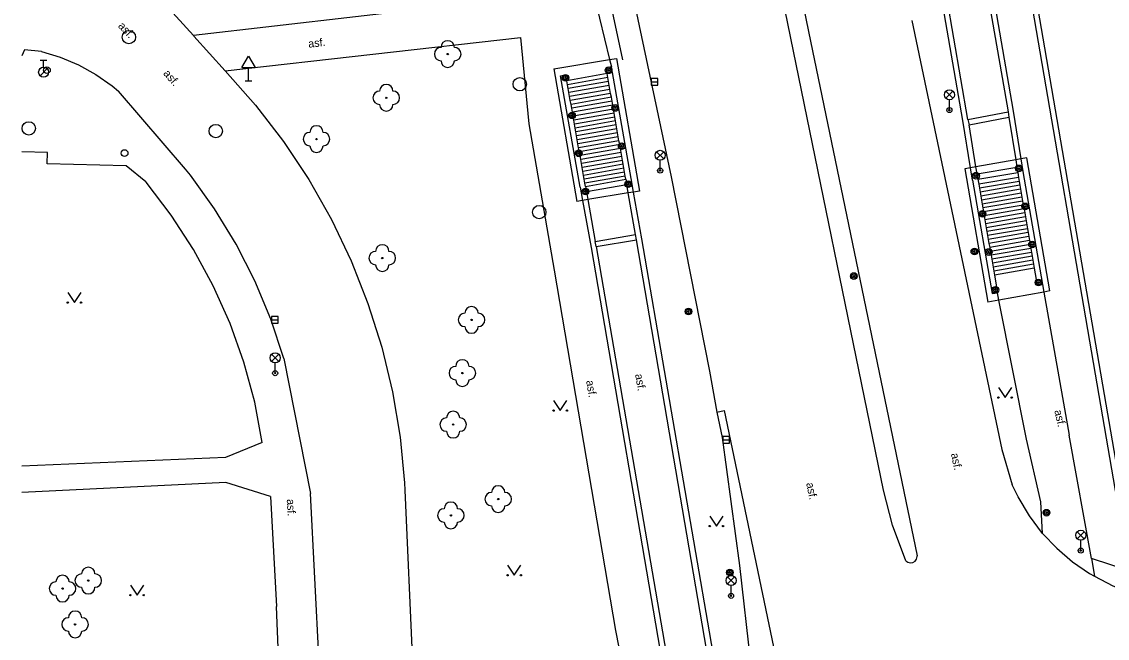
# Model space of a CAD drawing. Extents: x -640201 to -639641, y -1044739 to -1044317.
# Drawn here: x -640198.6 to -640117.2, y -1044403.5 to -1044357.3 of the extents above; entities that cross this region are included whole.
import ezdxf

# ---------------------------------------------------------------- set-up
doc = ezdxf.new("R2010")
doc.units = 0
for name, color, linetype in [('Budovy', 7, 'Continuous'), ('Ploty', 7, 'Continuous'), ('Popis povrchů', 7, 'Continuous'), ('Rozhraní ploch 1', 7, 'Continuous'), ('Rozhraní ploch 2', 7, 'Continuous'), ('Sloupy_označník', 7, 'Continuous'), ('Zeleň - stromy', 7, 'Continuous'), ('Znaky doprava', 7, 'Continuous'), ('Znaky kanalizace', 7, 'Continuous'), ('Znaky voda', 7, 'Continuous'), ('Značky doprava', 7, 'Continuous'), ('Značky KM', 7, 'Continuous')]:
    doc.layers.add(name, color=color, linetype=linetype)

msp = doc.modelspace()

# ---------------------------------------------------------------- linework, layer by layer
at = {"layer": 'Budovy'}
for p, q in [((-640158.67, -1044360.86), (-640154.493, -1044360.164)), ((-640154.493, -1044360.164), (-640153.99, -1044360.08)), ((-640153.99, -1044360.08), (-640152.26, -1044370.02)), ((-640158.67, -1044360.86), (-640156.94, -1044370.8)), ((-640123.673, -1044367.611), (-640124.067, -1044367.681)), ((-640123.22, -1044367.53), (-640123.673, -1044367.611)), ((-640121.5, -1044377.51), (-640123.22, -1044367.53)), ((-640127.44, -1044368.282), (-640127.88, -1044368.36)), ((-640127.88, -1044368.36), (-640126.16, -1044378.34)), ((-640127.046, -1044368.211), (-640127.44, -1044368.282)), ((-640124.067, -1044367.681), (-640127.046, -1044368.211)), ((-640152.707, -1044370.094), (-640153.102, -1044370.16)), ((-640152.26, -1044370.02), (-640152.707, -1044370.094)), ((-640156.522, -1044370.73), (-640156.94, -1044370.8)), ((-640156.127, -1044370.665), (-640156.522, -1044370.73)), ((-640153.102, -1044370.16), (-640156.127, -1044370.665)), ((-640125.321, -1044378.19), (-640126.16, -1044378.34)), ((-640121.954, -1044377.591), (-640125.321, -1044378.19)), ((-640121.5, -1044377.51), (-640121.954, -1044377.591))]:
    msp.add_line(p, q, dxfattribs=at)
at = {"layer": 'Ploty'}
for p, q in [((-640117.81, -1044385.35), (-640129.52, -1044317.039)), ((-640117.416, -1044385.282), (-640129.115, -1044317.039)), ((-640161.67, -1044321.76), (-640153.53, -1044360.18)), ((-640116.46, -1044393.19), (-640117.81, -1044385.35)), ((-640116.099, -1044392.931), (-640117.416, -1044385.282))]:
    msp.add_line(p, q, dxfattribs=at)
at = {"layer": 'Rozhraní ploch 1'}
for p, q in [((-640148.017, -1044317.039), (-640139.43, -1044358.78)), ((-640133.97, -1044392.45), (-640145.53, -1044336.09)), ((-640185.68, -1044358.36), (-640198.47, -1044344.26)), ((-640154.26, -1044348.23), (-640149.89, -1044368.95)), ((-640156.4, -1044352.32), (-640154.493, -1044360.164)), ((-640161.39, -1044355.53), (-640185.68, -1044358.36)), ((-640131.84, -1044357.24), (-640125.11, -1044389.4)), ((-640185.66, -1044358.4), (-640185.68, -1044358.36)), ((-640185.66, -1044358.4), (-640183.3, -1044361)), ((-640183.3, -1044361), (-640161.17, -1044358.52)), ((-640161.17, -1044358.52), (-640160.54, -1044364.97)), ((-640198.35, -1044359.43), (-640198.551, -1044359.883)), ((-640197.08, -1044359.55), (-640198.35, -1044359.43)), ((-640139.43, -1044358.78), (-640131.46, -1044397.37)), ((-640154.493, -1044360.164), (-640154.361, -1044360.705)), ((-640186.28, -1044368.37), (-640191.31, -1044362.52)), ((-640160.54, -1044364.97), (-640158.66, -1044375.94)), ((-640196.63, -1044367.14), (-640198.551, -1044367.08)), ((-640196.65, -1044367.99), (-640196.63, -1044367.14)), ((-640190.72, -1044368.14), (-640196.65, -1044367.99)), ((-640189.26, -1044369.33), (-640190.72, -1044368.14)), ((-640149.89, -1044368.95), (-640147.01, -1044383.51)), ((-640175.341, -1044372.157), (-640173.861, -1044375.259)), ((-640158.66, -1044375.94), (-640154.05, -1044402.97)), ((-640125.321, -1044378.19), (-640125.43, -1044377.64)), ((-640123.25, -1044388.62), (-640125.321, -1044378.19)), ((-640171.569, -1044381.734), (-640170.766, -1044385.076)), ((-640178.92, -1044382.57), (-640176.92, -1044392.68)), ((-640147.01, -1044383.51), (-640146.46, -1044386.59)), ((-640146.46, -1044386.59), (-640146.06, -1044388.49)), ((-640146.06, -1044388.49), (-640144.76, -1044398.09)), ((-640180.52, -1044388.87), (-640183.27, -1044389.99)), ((-640125.11, -1044389.4), (-640124.32, -1044392.04)), ((-640183.27, -1044389.99), (-640198.551, -1044390.649)), ((-640183.25, -1044391.86), (-640198.551, -1044392.622)), ((-640179.92, -1044392.92), (-640183.25, -1044391.86)), ((-640175.85, -1044413.58), (-640176.92, -1044392.68)), ((-640169.84, -1044392.43), (-640168.91, -1044413.2)), ((-640133.29, -1044395.07), (-640133.97, -1044392.45)), ((-640179.92, -1044392.92), (-640179.464, -1044401.167)), ((-640132.29, -1044397.73), (-640133.29, -1044395.07)), ((-640144.76, -1044398.09), (-640142.72, -1044416.01)), ((-640179.302, -1044404.884), (-640179.464, -1044401.167)), ((-640154.05, -1044402.97), (-640150.74, -1044420.12))]:
    msp.add_line(p, q, dxfattribs=at)
for points in [[(-640197.08, -1044359.55), (-640195.658, -1044359.977), (-640194.289, -1044360.555), (-640192.991, -1044361.276), (-640191.778, -1044362.133), (-640191.31, -1044362.52)], [(-640183.3, -1044361), (-640181.023, -1044363.574), (-640178.93, -1044366.3)], [(-640178.93, -1044366.3), (-640177.033, -1044369.166), (-640175.341, -1044372.157)], [(-640182.48, -1044373.993), (-640184.097, -1044371.346), (-640185.913, -1044368.832), (-640186.28, -1044368.37)], [(-640187.354, -1044371.818), (-640189.231, -1044369.364), (-640189.26, -1044369.33)], [(-640182.939, -1044379.944), (-640184.199, -1044377.123), (-640185.674, -1044374.409), (-640187.354, -1044371.818)], [(-640178.92, -1044382.57), (-640179.884, -1044379.622), (-640181.073, -1044376.757), (-640182.48, -1044373.993)], [(-640173.861, -1044375.259), (-640172.602, -1044378.457), (-640171.569, -1044381.734)], [(-640180.52, -1044388.87), (-640181.094, -1044385.835), (-640181.902, -1044382.853), (-640182.939, -1044379.944)], [(-640170.766, -1044385.076), (-640170.199, -1044388.466), (-640169.87, -1044391.887), (-640169.84, -1044392.43)], [(-640122.06, -1044395.68), (-640122.17, -1044393.32), (-640123.25, -1044388.62)], [(-640122.06, -1044395.68), (-640123.032, -1044394.36), (-640123.871, -1044392.951), (-640124.32, -1044392.04)], [(-640122.06, -1044395.68), (-640120.988, -1044396.801), (-640119.806, -1044397.805), (-640118.527, -1044398.682), (-640118.16, -1044398.9)], [(-640132.29, -1044397.73), (-640132.139, -1044397.85), (-640131.953, -1044397.9), (-640131.762, -1044397.871), (-640131.599, -1044397.767), (-640131.491, -1044397.607), (-640131.456, -1044397.417), (-640131.46, -1044397.37)], [(-640118.16, -1044398.9), (-640116.775, -1044399.601), (-640115.325, -1044400.155), (-640113.95, -1044400.53)]]:
    msp.add_lwpolyline(points, dxfattribs=at)
at = {"layer": 'Rozhraní ploch 2'}
for p, q in [((-640128.02, -1044364.74), (-640134.83, -1044325.32)), ((-640127.642, -1044364.668), (-640134.45, -1044325.26)), ((-640131.46, -1044324.72), (-640124.631, -1044364.093)), ((-640131.08, -1044324.64), (-640124.25, -1044364.02)), ((-640154.361, -1044360.705), (-640154.755, -1044360.774)), ((-640152.89, -1044369.07), (-640154.361, -1044360.705)), ((-640158.171, -1044361.374), (-640157.777, -1044361.304)), ((-640156.7, -1044369.74), (-640158.171, -1044361.374)), ((-640154.677, -1044361.22), (-640157.698, -1044361.751)), ((-640154.625, -1044361.515), (-640157.647, -1044362.046)), ((-640154.573, -1044361.811), (-640157.595, -1044362.342)), ((-640154.521, -1044362.106), (-640157.543, -1044362.637)), ((-640154.469, -1044362.402), (-640157.491, -1044362.933)), ((-640154.417, -1044362.697), (-640157.44, -1044363.228)), ((-640154.365, -1044362.993), (-640157.388, -1044363.524)), ((-640154.313, -1044363.288), (-640157.336, -1044363.819)), ((-640154.261, -1044363.584), (-640157.284, -1044364.115)), ((-640154.209, -1044363.879), (-640157.232, -1044364.41)), ((-640154.157, -1044364.175), (-640157.18, -1044364.706)), ((-640127.642, -1044364.668), (-640124.631, -1044364.093)), ((-640124.631, -1044364.093), (-640124.58, -1044364.49)), ((-640124.25, -1044364.02), (-640123.673, -1044367.611)), ((-640154.105, -1044364.47), (-640157.128, -1044365.001)), ((-640154.053, -1044364.766), (-640157.076, -1044365.297)), ((-640154.001, -1044365.061), (-640157.024, -1044365.592)), ((-640127.44, -1044368.282), (-640128.02, -1044364.74)), ((-640127.642, -1044364.668), (-640127.562, -1044365.06)), ((-640127.562, -1044365.06), (-640124.58, -1044364.49)), ((-640127.046, -1044368.211), (-640127.562, -1044365.06)), ((-640124.58, -1044364.49), (-640124.067, -1044367.681)), ((-640153.949, -1044365.357), (-640156.972, -1044365.888)), ((-640153.897, -1044365.652), (-640156.92, -1044366.183)), ((-640153.845, -1044365.948), (-640156.868, -1044366.479)), ((-640153.793, -1044366.243), (-640156.816, -1044366.774)), ((-640153.741, -1044366.538), (-640156.764, -1044367.069)), ((-640153.689, -1044366.834), (-640156.712, -1044367.365)), ((-640153.637, -1044367.129), (-640156.66, -1044367.66)), ((-640153.585, -1044367.425), (-640156.608, -1044367.956)), ((-640123.673, -1044367.611), (-640123.52, -1044368.56)), ((-640153.533, -1044367.72), (-640156.556, -1044368.251)), ((-640153.481, -1044368.016), (-640156.504, -1044368.547)), ((-640153.429, -1044368.311), (-640156.452, -1044368.842)), ((-640127.29, -1044369.2), (-640127.44, -1044368.282)), ((-640126.96, -1044368.739), (-640127.046, -1044368.211)), ((-640126.96, -1044368.739), (-640123.978, -1044368.232)), ((-640124.067, -1044367.681), (-640123.978, -1044368.232)), ((-640123.914, -1044368.627), (-640123.978, -1044368.232)), ((-640153.377, -1044368.607), (-640156.4, -1044369.138)), ((-640153.325, -1044368.902), (-640156.348, -1044369.433)), ((-640156.306, -1044369.671), (-640153.284, -1044369.139)), ((-640153.284, -1044369.139), (-640153.214, -1044369.533)), ((-640152.707, -1044370.094), (-640152.89, -1044369.07)), ((-640127.29, -1044369.2), (-640125.824, -1044377.707)), ((-640126.895, -1044369.133), (-640126.96, -1044368.739)), ((-640126.895, -1044369.133), (-640123.914, -1044368.627)), ((-640123.85, -1044368.999), (-640126.83, -1044369.516)), ((-640123.52, -1044368.56), (-640122.056, -1044377.013)), ((-640156.7, -1044369.74), (-640156.522, -1044370.73)), ((-640156.306, -1044369.671), (-640156.235, -1044370.064)), ((-640156.235, -1044370.064), (-640153.214, -1044369.533)), ((-640156.235, -1044370.064), (-640156.127, -1044370.665)), ((-640153.102, -1044370.16), (-640153.214, -1044369.533)), ((-640152.08, -1044373.6), (-640152.707, -1044370.094)), ((-640123.799, -1044369.294), (-640126.779, -1044369.811)), ((-640123.748, -1044369.59), (-640126.728, -1044370.107)), ((-640123.697, -1044369.885), (-640126.678, -1044370.402)), ((-640156.522, -1044370.73), (-640155.89, -1044374.25)), ((-640156.127, -1044370.665), (-640155.566, -1044373.789)), ((-640152.545, -1044373.274), (-640153.102, -1044370.16)), ((-640123.646, -1044370.181), (-640126.627, -1044370.698)), ((-640123.595, -1044370.476), (-640126.576, -1044370.993)), ((-640123.544, -1044370.772), (-640126.525, -1044371.289)), ((-640123.493, -1044371.068), (-640126.474, -1044371.585)), ((-640123.442, -1044371.363), (-640126.423, -1044371.88)), ((-640123.391, -1044371.659), (-640126.372, -1044372.176)), ((-640123.34, -1044371.954), (-640126.321, -1044372.471)), ((-640123.289, -1044372.25), (-640126.27, -1044372.767)), ((-640155.566, -1044373.789), (-640152.545, -1044373.274)), ((-640152.478, -1044373.668), (-640152.545, -1044373.274)), ((-640123.237, -1044372.546), (-640126.219, -1044373.063)), ((-640123.186, -1044372.841), (-640126.168, -1044373.358)), ((-640123.134, -1044373.137), (-640126.117, -1044373.655)), ((-640155.499, -1044374.183), (-640155.566, -1044373.789)), ((-640155.499, -1044374.183), (-640152.478, -1044373.668)), ((-640145.18, -1044416.46), (-640152.478, -1044373.668)), ((-640144.72, -1044416.38), (-640152.08, -1044373.6)), ((-640123.083, -1044373.432), (-640126.066, -1044373.95)), ((-640123.032, -1044373.728), (-640126.015, -1044374.246)), ((-640122.981, -1044374.023), (-640125.964, -1044374.541)), ((-640155.89, -1044374.25), (-640148.55, -1044417)), ((-640155.499, -1044374.183), (-640148.16, -1044416.93)), ((-640122.929, -1044374.319), (-640125.913, -1044374.837)), ((-640122.878, -1044374.615), (-640125.862, -1044375.133)), ((-640122.827, -1044374.91), (-640125.811, -1044375.428)), ((-640122.775, -1044375.206), (-640125.76, -1044375.724)), ((-640122.724, -1044375.501), (-640125.709, -1044376.019)), ((-640122.672, -1044375.797), (-640125.658, -1044376.315)), ((-640122.45, -1044377.08), (-640122.056, -1044377.013)), ((-640122.056, -1044377.013), (-640121.954, -1044377.591)), ((-640125.824, -1044377.707), (-640125.43, -1044377.64)), ((-640121.954, -1044377.591), (-640120.06, -1044388.32)), ((-640146.46, -1044386.59), (-640145.92, -1044386.47)), ((-640145.92, -1044386.47), (-640137.78, -1044425.48)), ((-640118.39, -1044397.57), (-640120.06, -1044388.32)), ((-640115.48, -1044398.51), (-640118.39, -1044397.57)), ((-640118.39, -1044397.57), (-640118.16, -1044398.9))]:
    msp.add_line(p, q, dxfattribs=at)
for points in [[(-640153.284, -1044369.139), (-640153.325, -1044368.902), (-640153.377, -1044368.607), (-640153.429, -1044368.311), (-640153.481, -1044368.016), (-640153.533, -1044367.72), (-640153.585, -1044367.425), (-640153.637, -1044367.129), (-640153.689, -1044366.834), (-640153.741, -1044366.538), (-640153.793, -1044366.243), (-640153.845, -1044365.948), (-640153.897, -1044365.652), (-640153.949, -1044365.357), (-640154.001, -1044365.061), (-640154.053, -1044364.766), (-640154.105, -1044364.47), (-640154.157, -1044364.175), (-640154.209, -1044363.879), (-640154.261, -1044363.584), (-640154.313, -1044363.288), (-640154.365, -1044362.993), (-640154.417, -1044362.697), (-640154.469, -1044362.402), (-640154.521, -1044362.106), (-640154.573, -1044361.811), (-640154.625, -1044361.515), (-640154.677, -1044361.22), (-640154.755, -1044360.774)], [(-640156.306, -1044369.671), (-640156.348, -1044369.433), (-640156.4, -1044369.138), (-640156.452, -1044368.842), (-640156.504, -1044368.547), (-640156.556, -1044368.251), (-640156.608, -1044367.956), (-640156.66, -1044367.66), (-640156.712, -1044367.365), (-640156.764, -1044367.069), (-640156.816, -1044366.774), (-640156.868, -1044366.479), (-640156.92, -1044366.183), (-640156.972, -1044365.888), (-640157.024, -1044365.592), (-640157.076, -1044365.297), (-640157.128, -1044365.001), (-640157.18, -1044364.706), (-640157.232, -1044364.41), (-640157.284, -1044364.115), (-640157.336, -1044363.819), (-640157.388, -1044363.524), (-640157.44, -1044363.228), (-640157.491, -1044362.933), (-640157.543, -1044362.637), (-640157.595, -1044362.342), (-640157.647, -1044362.046), (-640157.698, -1044361.751), (-640157.777, -1044361.304)], [(-640126.895, -1044369.133), (-640126.83, -1044369.516), (-640126.779, -1044369.811), (-640126.728, -1044370.107), (-640126.678, -1044370.402), (-640126.627, -1044370.698), (-640126.576, -1044370.993), (-640126.525, -1044371.289), (-640126.474, -1044371.585), (-640126.423, -1044371.88), (-640126.372, -1044372.176), (-640126.321, -1044372.471), (-640126.27, -1044372.767), (-640126.219, -1044373.063), (-640126.168, -1044373.358), (-640126.117, -1044373.655), (-640126.066, -1044373.95), (-640126.015, -1044374.246), (-640125.964, -1044374.541), (-640125.913, -1044374.837), (-640125.862, -1044375.133), (-640125.811, -1044375.428), (-640125.76, -1044375.724), (-640125.709, -1044376.019), (-640125.658, -1044376.315), (-640125.43, -1044377.64)], [(-640123.914, -1044368.627), (-640123.85, -1044368.999), (-640123.799, -1044369.294), (-640123.748, -1044369.59), (-640123.697, -1044369.885), (-640123.646, -1044370.181), (-640123.595, -1044370.476), (-640123.544, -1044370.772), (-640123.493, -1044371.068), (-640123.442, -1044371.363), (-640123.391, -1044371.659), (-640123.34, -1044371.954), (-640123.289, -1044372.25), (-640123.237, -1044372.546), (-640123.186, -1044372.841), (-640123.134, -1044373.137), (-640123.083, -1044373.432), (-640123.032, -1044373.728), (-640122.981, -1044374.023), (-640122.929, -1044374.319), (-640122.878, -1044374.615), (-640122.827, -1044374.91), (-640122.775, -1044375.206), (-640122.724, -1044375.501), (-640122.672, -1044375.797), (-640122.45, -1044377.08)]]:
    msp.add_lwpolyline(points, dxfattribs=at)
at = {"layer": 'Sloupy_označník'}
for centre, radius in [((-640154.57, -1044360.97), 0.25), ((-640154.57, -1044360.97), 0.158), ((-640154.57, -1044360.97), 0.05), ((-640157.8, -1044361.53), 0.25), ((-640157.8, -1044361.53), 0.158), ((-640157.8, -1044361.53), 0.05), ((-640154.08, -1044363.79), 0.25), ((-640157.31, -1044364.36), 0.25), ((-640157.31, -1044364.36), 0.158), ((-640157.31, -1044364.36), 0.05), ((-640154.08, -1044363.79), 0.158), ((-640154.08, -1044363.79), 0.05), ((-640153.59, -1044366.65), 0.25), ((-640153.59, -1044366.65), 0.158), ((-640153.59, -1044366.65), 0.05), ((-640156.81, -1044367.19), 0.25), ((-640156.81, -1044367.19), 0.158), ((-640156.81, -1044367.19), 0.05), ((-640123.83, -1044368.32), 0.25), ((-640123.83, -1044368.32), 0.158), ((-640123.83, -1044368.32), 0.05), ((-640153.1, -1044369.5), 0.25), ((-640127.04, -1044368.87), 0.25), ((-640127.04, -1044368.87), 0.158), ((-640127.04, -1044368.87), 0.05), ((-640156.31, -1044370.05), 0.25), ((-640156.31, -1044370.05), 0.158), ((-640156.31, -1044370.05), 0.05), ((-640153.1, -1044369.5), 0.158), ((-640153.1, -1044369.5), 0.05), ((-640126.56, -1044371.73), 0.25), ((-640126.56, -1044371.73), 0.158), ((-640126.56, -1044371.73), 0.05), ((-640123.35, -1044371.17), 0.25), ((-640123.35, -1044371.17), 0.158), ((-640123.35, -1044371.17), 0.05), ((-640122.84, -1044374.02), 0.25), ((-640122.84, -1044374.02), 0.158), ((-640122.84, -1044374.02), 0.05), ((-640127.16, -1044374.55), 0.25), ((-640127.16, -1044374.55), 0.158), ((-640127.16, -1044374.55), 0.05), ((-640126.09, -1044374.59), 0.25), ((-640126.09, -1044374.59), 0.158), ((-640126.09, -1044374.59), 0.05), ((-640136.19, -1044376.39), 0.25), ((-640136.19, -1044376.39), 0.158), ((-640136.19, -1044376.39), 0.05), ((-640125.59, -1044377.42), 0.25), ((-640125.59, -1044377.42), 0.158), ((-640125.59, -1044377.42), 0.05), ((-640122.35, -1044376.87), 0.25), ((-640122.35, -1044376.87), 0.158), ((-640122.35, -1044376.87), 0.05), ((-640148.59, -1044379.05), 0.25), ((-640148.59, -1044379.05), 0.158), ((-640148.59, -1044379.05), 0.05), ((-640121.75, -1044394.13), 0.25), ((-640121.75, -1044394.13), 0.158), ((-640121.75, -1044394.13), 0.05), ((-640145.49, -1044398.61), 0.25), ((-640145.49, -1044398.61), 0.158), ((-640145.49, -1044398.61), 0.05)]:
    msp.add_circle(centre, radius, dxfattribs=at)
at = {"layer": 'Zeleň - stromy'}
for centre in [(-640166.63, -1044359.75), (-640171.23, -1044363.03), (-640176.46, -1044366.12), (-640171.53, -1044375.04), (-640164.84, -1044379.68), (-640165.53, -1044383.66), (-640166.22, -1044387.53), (-640162.84, -1044393.11), (-640166.39, -1044394.33), (-640193.56, -1044399.22), (-640195.49, -1044399.82), (-640194.55, -1044402.5)]:
    msp.add_circle(centre, 0.05, dxfattribs=at)
for centre, start, end in [((-640167.13, -1044359.75), 90, 270), ((-640166.63, -1044359.25), 0, 180), ((-640166.13, -1044359.75), 270, 90), ((-640166.63, -1044360.25), 180, 0), ((-640171.73, -1044363.03), 90, 270), ((-640171.23, -1044362.53), 0, 180), ((-640170.73, -1044363.03), 270, 90), ((-640171.23, -1044363.53), 180, 0), ((-640176.46, -1044365.62), 0, 180), ((-640176.96, -1044366.12), 90, 270), ((-640175.96, -1044366.12), 270, 90), ((-640176.46, -1044366.62), 180, 0), ((-640171.53, -1044374.54), 0, 180), ((-640172.03, -1044375.04), 90, 270), ((-640171.03, -1044375.04), 270, 90), ((-640171.53, -1044375.54), 180, 0), ((-640164.84, -1044379.18), 0, 180), ((-640165.34, -1044379.68), 90, 270), ((-640164.34, -1044379.68), 270, 90), ((-640164.84, -1044380.18), 180, 0), ((-640165.53, -1044383.16), 0, 180), ((-640166.03, -1044383.66), 90, 270), ((-640165.03, -1044383.66), 270, 90), ((-640165.53, -1044384.16), 180, 0), ((-640166.72, -1044387.53), 90, 270), ((-640166.22, -1044387.03), 0, 180), ((-640165.72, -1044387.53), 270, 90), ((-640166.22, -1044388.03), 180, 0), ((-640163.34, -1044393.11), 90, 270), ((-640162.84, -1044392.61), 0, 180), ((-640162.34, -1044393.11), 270, 90), ((-640166.39, -1044393.83), 0, 180), ((-640162.84, -1044393.61), 180, 0), ((-640166.89, -1044394.33), 90, 270), ((-640165.89, -1044394.33), 270, 90), ((-640166.39, -1044394.83), 180, 0), ((-640193.56, -1044398.72), 0, 180), ((-640195.99, -1044399.82), 90, 270), ((-640195.49, -1044399.32), 0, 180), ((-640194.99, -1044399.82), 270, 90), ((-640194.06, -1044399.22), 90, 270), ((-640193.06, -1044399.22), 270, 90), ((-640193.56, -1044399.72), 180, 0), ((-640195.49, -1044400.32), 180, 0), ((-640194.55, -1044402), 0, 180), ((-640195.05, -1044402.5), 90, 270), ((-640194.05, -1044402.5), 270, 90), ((-640194.55, -1044403), 180, 0)]:
    msp.add_arc(centre, 0.5, start, end, dxfattribs=at)
at = {"layer": 'Znaky doprava'}
for p, q in [((-640129.295, -1044362.535), (-640128.765, -1044363.065)), ((-640129.295, -1044363.065), (-640128.765, -1044362.535)), ((-640129.03, -1044363.95), (-640129.03, -1044363.175)), ((-640150.975, -1044367.075), (-640150.445, -1044367.605)), ((-640150.975, -1044367.605), (-640150.445, -1044367.075)), ((-640150.71, -1044368.49), (-640150.71, -1044367.715)), ((-640179.825, -1044382.255), (-640179.295, -1044382.785)), ((-640179.825, -1044382.785), (-640179.295, -1044382.255)), ((-640179.56, -1044383.67), (-640179.56, -1044382.895)), ((-640119.455, -1044395.555), (-640118.925, -1044396.085)), ((-640119.455, -1044396.085), (-640118.925, -1044395.555)), ((-640119.19, -1044396.97), (-640119.19, -1044396.195)), ((-640145.655, -1044398.945), (-640145.125, -1044399.475)), ((-640145.655, -1044399.475), (-640145.125, -1044398.945)), ((-640145.39, -1044400.36), (-640145.39, -1044399.585))]:
    msp.add_line(p, q, dxfattribs=at)
for centre, radius in [((-640129.03, -1044362.8), 0.375), ((-640129.03, -1044363.95), 0.19), ((-640129.03, -1044363.95), 0.05), ((-640150.71, -1044367.34), 0.375), ((-640150.71, -1044368.49), 0.19), ((-640150.71, -1044368.49), 0.05), ((-640179.56, -1044382.52), 0.375), ((-640179.56, -1044383.67), 0.19), ((-640179.56, -1044383.67), 0.05), ((-640119.19, -1044395.82), 0.375), ((-640119.19, -1044396.97), 0.19), ((-640119.19, -1044396.97), 0.05), ((-640145.39, -1044399.21), 0.375), ((-640145.39, -1044400.36), 0.19), ((-640145.39, -1044400.36), 0.05)]:
    msp.add_circle(centre, radius, dxfattribs=at)
at = {"layer": 'Znaky kanalizace'}
for p, q in [((-640151.39, -1044361.83), (-640150.89, -1044361.83)), ((-640179.83, -1044379.68), (-640179.33, -1044379.68)), ((-640146.02, -1044388.68), (-640145.52, -1044388.68))]:
    msp.add_line(p, q, dxfattribs=at)
for points in [[(-640151.39, -1044362.08), (-640150.89, -1044362.08), (-640150.89, -1044361.58), (-640151.39, -1044361.58)], [(-640179.83, -1044379.93), (-640179.33, -1044379.93), (-640179.33, -1044379.43), (-640179.83, -1044379.43)], [(-640146.02, -1044388.93), (-640145.52, -1044388.93), (-640145.52, -1044388.43), (-640146.02, -1044388.43)]]:
    msp.add_lwpolyline(points, close=True, dxfattribs=at)
for centre in [(-640190.52, -1044358.48), (-640161.23, -1044362.01), (-640198.02, -1044365.32), (-640184.01, -1044365.52), (-640159.77, -1044371.6)]:
    msp.add_circle(centre, 0.5, dxfattribs=at)
at = {"layer": 'Znaky voda'}
for p, q in [((-640197.16, -1044360.21), (-640196.66, -1044360.21)), ((-640196.91, -1044360.735), (-640196.91, -1044360.21)), ((-640197.175, -1044361.375), (-640196.645, -1044360.845))]:
    msp.add_line(p, q, dxfattribs=at)
for centre, radius in [((-640196.91, -1044361.11), 0.375), ((-640196.66, -1044360.96), 0.25), ((-640190.84, -1044367.17), 0.25)]:
    msp.add_circle(centre, radius, dxfattribs=at)
at = {"layer": 'Značky doprava'}
for p, q in [((-640182.06, -1044360.76), (-640181.56, -1044359.91)), ((-640181.56, -1044359.91), (-640181.06, -1044360.76)), ((-640182.06, -1044360.76), (-640181.06, -1044360.76)), ((-640181.56, -1044361.76), (-640181.56, -1044360.76)), ((-640181.81, -1044361.76), (-640181.31, -1044361.76))]:
    msp.add_line(p, q, dxfattribs=at)
at = {"layer": 'Značky KM'}
for p, q in [((-640195.1, -1044377.629), (-640194.6, -1044378.379)), ((-640194.6, -1044378.379), (-640194.1, -1044377.629)), ((-640125.363, -1044384.749), (-640124.863, -1044385.499)), ((-640124.863, -1044385.499), (-640124.363, -1044384.749)), ((-640158.698, -1044385.729), (-640158.198, -1044386.479)), ((-640158.198, -1044386.479), (-640157.698, -1044385.729)), ((-640146.992, -1044394.381), (-640146.492, -1044395.131)), ((-640146.492, -1044395.131), (-640145.992, -1044394.381)), ((-640162.142, -1044398.066), (-640161.642, -1044398.816)), ((-640161.642, -1044398.816), (-640161.142, -1044398.066)), ((-640190.411, -1044399.561), (-640189.911, -1044400.311)), ((-640189.911, -1044400.311), (-640189.411, -1044399.561))]:
    msp.add_line(p, q, dxfattribs=at)
for centre in [(-640195.1, -1044378.379), (-640194.1, -1044378.379), (-640125.363, -1044385.499), (-640124.363, -1044385.499), (-640158.698, -1044386.479), (-640157.698, -1044386.479), (-640146.992, -1044395.131), (-640145.992, -1044395.131), (-640162.142, -1044398.816), (-640161.142, -1044398.816), (-640190.411, -1044400.311), (-640189.411, -1044400.311)]:
    msp.add_circle(centre, 0.05, dxfattribs=at)

# ---------------------------------------------------------------- texts
at = {"layer": 'Popis povrchů'}
for rotation, p in [(313.152, (-640191.37, -1044357.68)), (6.39418, (-640177.048, -1044359.28)), (310.6899, (-640187.982, -1044361.227)), (279.74246, (-640152.589, -1044383.772)), (279.462, (-640156.26, -1044384.25)), (282.94119, (-640121.174, -1044386.491)), (281.66924, (-640128.924, -1044389.718)), (281.78647, (-640139.772, -1044391.933)), (273.16482, (-640178.688, -1044393.122))]:
    msp.add_text('asf.', height=0.6, rotation=rotation, dxfattribs=at).set_placement(p)

doc.saveas('drawing.dxf')
